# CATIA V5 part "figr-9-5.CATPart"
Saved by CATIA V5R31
Part number: Part1
Bounding box of the stored display mesh (mm): x -71.324 to 69.61, y -211.059 to 0, z 0 to 45
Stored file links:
  D:\PROJECTS\Project 2021\US EDITION\CATIA V5 6R 2021\Resources\Part Files\c09_catia_v5_6r2021_prt\c09_catia_v5_6r2021_prt\figr-9-5.CATPart
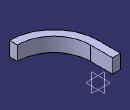
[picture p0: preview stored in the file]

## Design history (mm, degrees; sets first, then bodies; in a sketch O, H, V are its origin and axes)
Body1 (main body)
  Sketch1 on xy-plane, origin (0, 0, 0), H (1, 0, 0), V (0, 1, 0)
    line L1 (0, 0) -> (0, -70.1255)
    arc A1 centre (69.6095, -70.1255) radius 69.6095 from (0, -70.1255) to (69.6095, -139.7351) ccw
    vertical: L1 V
    tangency: A1 L1
  Sketch2 on zx-plane, origin (0, 0, 0), H (-1, 0, 0), V (0, 0, 1)
    point P1 (46.3244, 0)
    line L1 (46.3244, 0) -> (71.3244, 0)
    line L2 (71.3244, 0) -> (71.3244, 45)
    line L3 (71.3244, 45) -> (46.3244, 45)
    line L4 (46.3244, 45) -> (46.3244, 0)
    length L3 = 25
    length L2 = 45
    coincidence: P1 H
    horizontal: L1 H, L3 H
    vertical: L2 V, L4 V
  Rib1: profile Sketch2, centre curve Sketch1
